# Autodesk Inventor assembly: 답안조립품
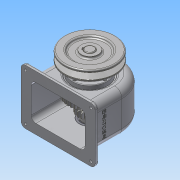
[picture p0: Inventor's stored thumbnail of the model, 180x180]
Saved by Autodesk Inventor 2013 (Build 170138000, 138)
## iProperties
Created: 2016-01
Part Number: 답안조립품
Document SubType Name: Assembly
Designer: Administrator
Author: Administrator
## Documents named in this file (16)
- C:\Users\Administrator\Desktop\460106V1026\답안조립품.iam
- C:\Users\Administrator\Desktop\460106V1026\V-벨트풀리.ipt
- C:\Users\Administrator\Desktop\460106V1026\뒤커버.ipt
- C:\Users\Administrator\Desktop\460106V1026\멈춤나사 - M4x10.ipt
- C:\Users\Administrator\Desktop\460106V1026\베어링 6203.ipt
- C:\Users\Administrator\Desktop\460106V1026\본체.ipt
- C:\Users\Administrator\Desktop\460106V1026\볼트 M3 x 8.ipt
- C:\Users\Administrator\Desktop\460106V1026\볼트 M3 x 10.ipt
- C:\Users\Administrator\Desktop\460106V1026\부시1.ipt
- C:\Users\Administrator\Desktop\460106V1026\부시2.ipt
- C:\Users\Administrator\Desktop\460106V1026\스퍼기어.ipt
- C:\Users\Administrator\Desktop\460106V1026\앞커버.ipt
- C:\Users\Administrator\Desktop\460106V1026\오일씰 28 40 8.ipt
- C:\Users\Administrator\Desktop\460106V1026\축.ipt
- C:\Users\Administrator\Desktop\460106V1026\키 - 5 x 5 x 18.ipt
- C:\Users\Administrator\Desktop\460106V1026\키 - 6 x 6 x 22.ipt
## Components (9 placed, 3 different names)
1. V-벨트풀리:1
2. ISO 4762 M3 x 8:1
3. ISO 4762 M3 x 8:2
4. ISO 4762 M3 x 8:3
5. ISO 4762 M3 x 8:4
6. ISO 4762 M3 x 10:1
7. ISO 4762 M3 x 10:2
8. ISO 4762 M3 x 10:3
9. ISO 4762 M3 x 10:4
